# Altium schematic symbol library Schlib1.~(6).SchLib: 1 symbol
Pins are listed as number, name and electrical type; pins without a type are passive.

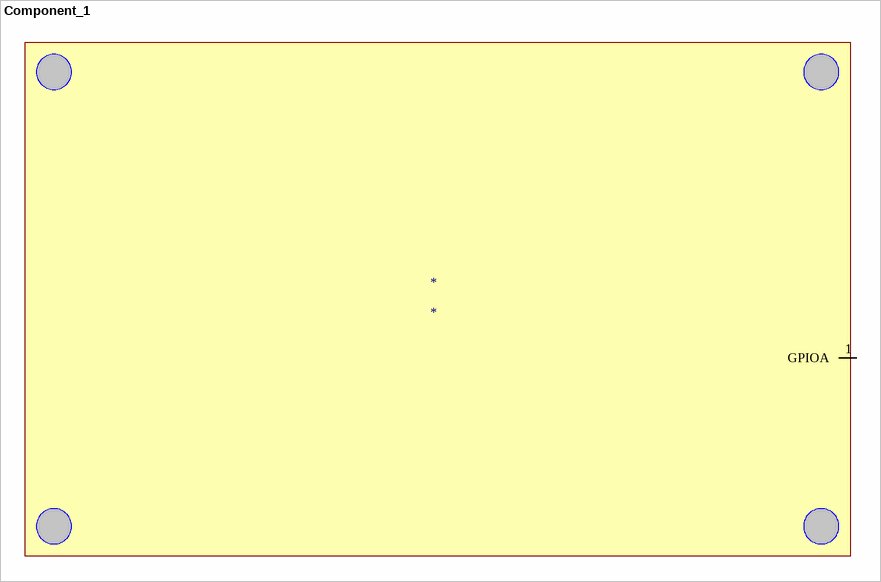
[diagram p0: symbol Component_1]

## Component_1
designator *
footprint PYNQZ2_board
pins: 1 GPIOA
